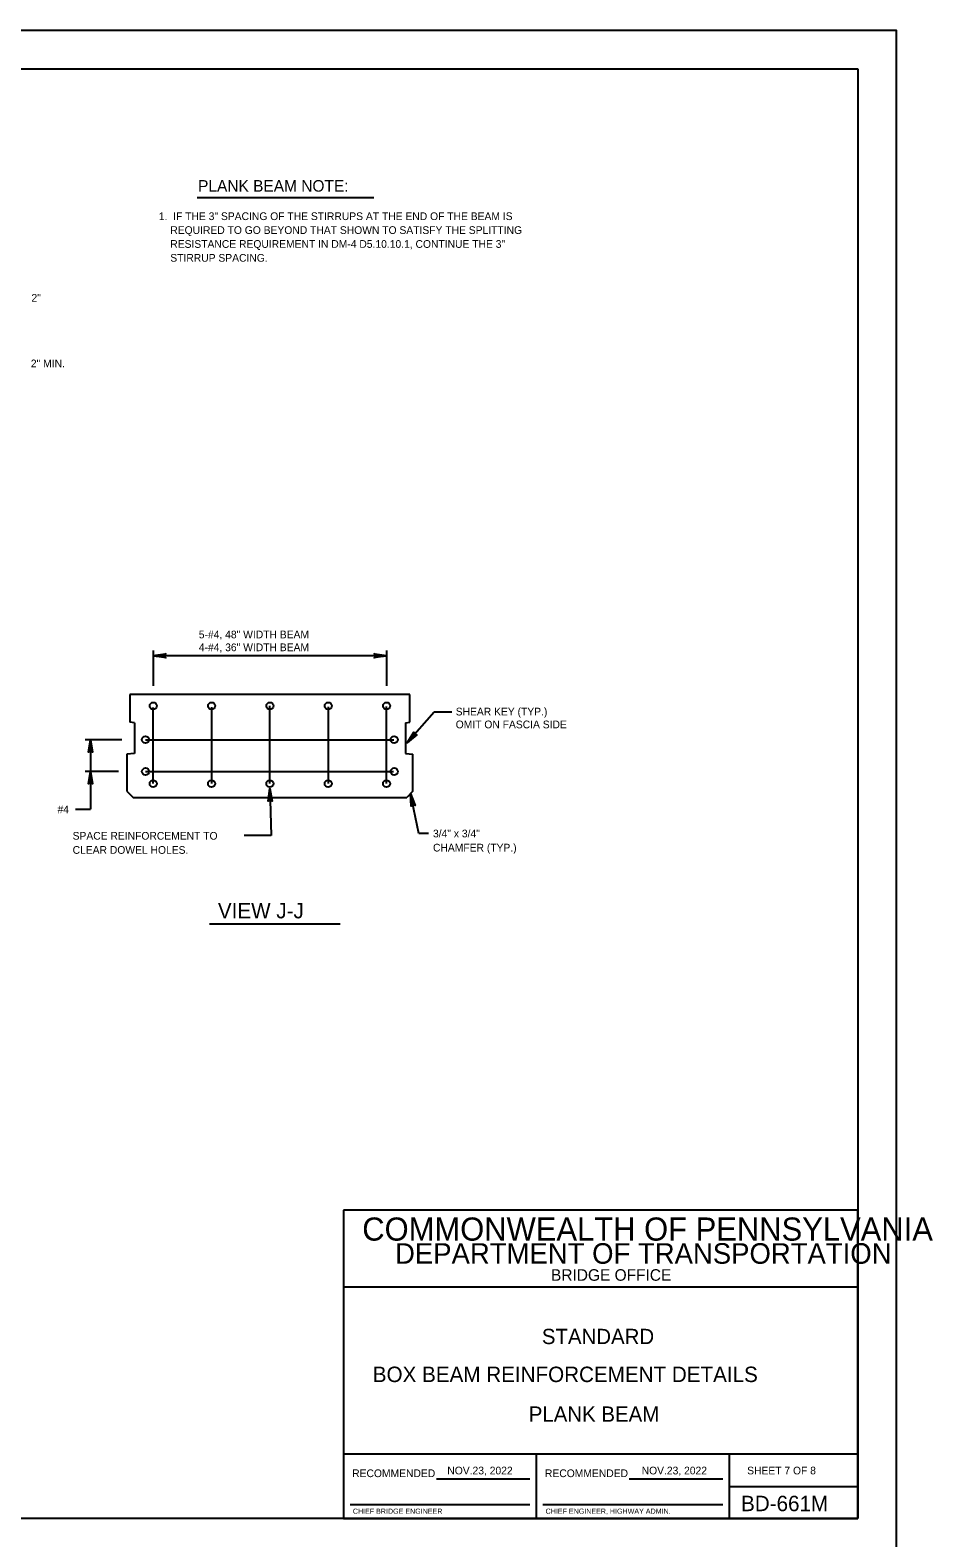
# Model space of a CAD drawing. Extents: x 639331 to 643089, y 299088 to 300975.
# Drawn here: x 642738 to 643089, y 300283 to 300870 of the extents above; entities that cross this region are included whole.
import ezdxf

# ---------------------------------------------------------------- set-up
doc = ezdxf.new("R2010")
doc.units = 0
for name, color, linetype in [('1', 7, 'Continuous'), ('DATES', 7, 'Continuous'), ('PLT-BNDY', 7, 'Continuous'), ('SIGNATORY TITLES', 7, 'Continuous')]:
    doc.layers.add(name, color=color, linetype=linetype)

msp = doc.modelspace()

# ---------------------------------------------------------------- linework, layer by layer
at = {"layer": '1'}
for p, q in [((642274.06, 300854.66), (643060.06, 300854.66)), ((643060.06, 300854.66), (643060.06, 300290.66)), ((642871.79, 300804.39), (642803.06, 300804.39)), ((642786, 300628.33), (642786, 300614.66)), ((642876.76, 300628.33), (642876.76, 300614.66)), ((642876.76, 300626.31), (642786, 300626.31)), ((642885.83, 300611.25), (642776.93, 300611.25)), ((642776.93, 300611.25), (642776.93, 300600.42)), ((642885.83, 300600.42), (642885.83, 300611.25)), ((642786, 300576.55), (642786, 300606.12)), ((642808.69, 300606.25), (642808.69, 300576.55)), ((642831.38, 300576.55), (642831.38, 300606.78)), ((642854.07, 300606.38), (642854.07, 300576.55)), ((642876.76, 300576.55), (642876.76, 300606.51)), ((642778.65, 300600.21), (642776.93, 300600.42)), ((642778.65, 300600.21), (642778.65, 300588.24)), ((642884.1, 300600.21), (642885.83, 300600.42)), ((642884.1, 300600.21), (642884.1, 300588.24)), ((642895.28, 300604.33), (642884.78, 300592.48)), ((642902.1, 300604.33), (642895.28, 300604.33)), ((642773.78, 300593.65), (642759.49, 300593.65)), ((642761.61, 300593.65), (642761.61, 300566.65)), ((642783, 300593.65), (642879.56, 300593.65)), ((642778.65, 300588.24), (642775.73, 300588.06)), ((642775.73, 300588.06), (642775.73, 300573.58)), ((642884.1, 300588.24), (642887.03, 300588.06)), ((642887.03, 300573.58), (642887.03, 300588.06)), ((642772.48, 300581.26), (642759.49, 300581.26)), ((642783, 300581.26), (642879.43, 300581.26)), ((642775.73, 300573.58), (642778.13, 300571.18)), ((642778.13, 300571.18), (642884.63, 300571.18)), ((642831.33, 300574.61), (642831.85, 300556.43)), ((642887.03, 300573.58), (642884.63, 300571.18)), ((642889.29, 300557.11), (642886.14, 300572.69)), ((642755.77, 300566.65), (642761.61, 300566.65)), ((642831.85, 300556.43), (642821.33, 300556.43)), ((642893.03, 300557.11), (642889.29, 300557.11)), ((642858.76, 300521.83), (642807.88, 300521.83)), ((643060.06, 300410.66), (642860.06, 300410.66)), ((642860.06, 300410.66), (642860.06, 300290.66)), ((643060.06, 300290.66), (643060.06, 300410.66)), ((643060.06, 300380.66), (642860.06, 300380.66)), ((643060.06, 300315.66), (642860.06, 300315.66)), ((642935.06, 300290.66), (642935.06, 300315.66)), ((643010.06, 300315.66), (643010.06, 300290.66)), ((642896.15, 300306.16), (642932.56, 300306.16)), ((642971.15, 300306.16), (643007.56, 300306.16)), ((643010.06, 300303.16), (643060.06, 300303.16)), ((642862.56, 300296.16), (642932.56, 300296.16)), ((642937.56, 300296.16), (643007.56, 300296.16)), ((643060.06, 300290.66), (642274.06, 300290.66)), ((642860.06, 300290.66), (643060.06, 300290.66))]:
    msp.add_line(p, q, dxfattribs=at)
for points in [[(642790.61, 300625.73), (642790.44, 300626.06), (642786, 300626.31), (642790.61, 300625.73), (642790.85, 300625.53), (642786, 300626.31), (642790.44, 300626.53), (642790.6, 300626.86), (642786, 300626.31), (642790.85, 300627.08), (642790.6, 300626.86)], [(642872.14, 300626.89), (642872.31, 300626.55), (642876.76, 300626.31), (642872.14, 300626.89), (642871.91, 300627.09), (642876.76, 300626.31), (642872.32, 300626.09), (642872.16, 300625.76), (642876.76, 300626.31), (642871.91, 300625.54), (642872.16, 300625.76)], [(642761.03, 300589.04), (642761.37, 300589.21), (642761.61, 300593.65), (642761.03, 300589.04), (642760.83, 300588.8), (642761.61, 300593.65), (642761.83, 300589.22), (642762.16, 300589.05), (642761.61, 300593.65), (642762.38, 300588.8), (642762.16, 300589.05)], [(642888.27, 300595.55), (642887.91, 300595.64), (642884.78, 300592.48), (642888.27, 300595.55), (642888.58, 300595.59), (642884.78, 300592.48), (642887.56, 300595.95), (642887.42, 300596.29), (642884.78, 300592.48), (642887.42, 300596.62), (642887.42, 300596.29)], [(642761.03, 300576.64), (642761.37, 300576.82), (642761.61, 300581.26), (642761.03, 300576.64), (642760.83, 300576.41), (642761.61, 300581.26), (642761.83, 300576.82), (642762.16, 300576.66), (642761.61, 300581.26), (642762.38, 300576.41), (642762.16, 300576.66)], [(642830.86, 300569.98), (642831.19, 300570.16), (642831.33, 300574.61), (642830.86, 300569.98), (642830.66, 300569.74), (642831.33, 300574.61), (642831.65, 300570.18), (642831.99, 300570.02), (642831.33, 300574.61), (642832.22, 300569.78), (642831.99, 300570.02)], [(642886.48, 300568.05), (642886.78, 300568.29), (642886.14, 300572.69), (642886.48, 300568.05), (642886.33, 300567.78), (642886.14, 300572.69), (642887.23, 300568.38), (642887.59, 300568.29), (642886.14, 300572.69), (642887.85, 300568.09), (642887.59, 300568.29)]]:
    msp.add_lwpolyline(points, dxfattribs=at)
for centre in [(642786, 300606.78), (642808.69, 300606.78), (642831.38, 300606.78), (642854.07, 300606.78), (642876.76, 300606.78), (642783, 300593.65), (642879.76, 300593.65), (642783, 300581.26), (642879.76, 300581.26), (642786, 300576.55), (642808.69, 300576.55), (642831.38, 300576.55), (642854.07, 300576.55), (642876.76, 300576.55)]:
    msp.add_circle(centre, 1.38, dxfattribs=at)
at = {"layer": 'PLT-BNDY'}
msp.add_lwpolyline([(642234.06, 300869.66), (643075.06, 300869.66), (643075.06, 300275.66), (642234.06, 300275.66)], close=True, dxfattribs=at)

# ---------------------------------------------------------------- texts
at = {"layer": '1'}
for s, height, p in [('PLANK BEAM NOTE:', 4.5, (642803.45, 300806.83)), ('1.  IF THE 3" SPACING OF THE STIRRUPS AT THE END OF THE BEAM IS', 3, (642788.17, 300795.78)), ('    REQUIRED TO GO BEYOND THAT SHOWN TO SATISFY THE SPLITTING', 3, (642788.17, 300790.38)), ('    RESISTANCE REQUIREMENT IN DM-4 D5.10.10.1, CONTINUE THE 3" ', 3, (642788.17, 300784.98)), ('    STIRRUP SPACING.', 3, (642788.17, 300779.58)), ('2"', 3, (642738.62, 300764)), ('2" MIN.', 3, (642738.38, 300738.51)), ('5-#4, 48" WIDTH BEAM', 3, (642803.72, 300633.07)), ('4-#4, 36" WIDTH BEAM', 3, (642803.72, 300628.07)), ('SHEAR KEY (TYP.)', 3, (642903.66, 300603.08)), ('OMIT ON FASCIA SIDE', 3, (642903.66, 300598.08)), ('#4', 3, (642748.75, 300565.04)), ('SPACE REINFORCEMENT TO', 3, (642754.63, 300554.75)), ('3/4" x 3/4"', 3, (642894.83, 300555.65)), ('CLEAR DOWEL HOLES.', 3, (642754.63, 300549.25)), ('CHAMFER (TYP.)', 3, (642894.83, 300550.15)), ('COMMONWEALTH OF PENNSYLVANIA', 9, (642867.31, 300398.78)), ('DEPARTMENT OF TRANSPORTATION', 8.0002, (642880.06, 300389.78)), ('BRIDGE OFFICE', 4.5, (642940.74, 300383.16)), ('STANDARD', 5.939, (642937.18, 300358.53)), ('BOX BEAM REINFORCEMENT DETAILS', 6, (642871.41, 300343.76)), ('PLANK BEAM', 5.939, (642932.09, 300328.33)), ('RECOMMENDED', 3, (642863.39, 300306.78)), ('RECOMMENDED', 3, (642938.39, 300306.78)), ('SHEET 7 OF 8', 3, (643017.05, 300307.84)), ('BD-661M', 6, (643014.68, 300293.53))]:
    msp.add_text(s, height=height, dxfattribs=at).set_placement(p)
msp.add_text('VIEW J-J', height=6, rotation=360, dxfattribs=at).set_placement((642811.15, 300524.15))
at = {"layer": 'DATES'}
for p in [(642900.4, 300307.84), (642976.01, 300307.84)]:
    msp.add_text('NOV.23, 2022', height=3, dxfattribs=at).set_placement(p)
at = {"layer": 'SIGNATORY TITLES'}
for s, p in [('CHIEF BRIDGE ENGINEER', (642863.65, 300292.53)), ('CHIEF ENGINEER, HIGHWAY ADMIN.', (642938.65, 300292.53))]:
    msp.add_text(s, height=2, dxfattribs=at).set_placement(p)

doc.saveas('drawing.dxf')
